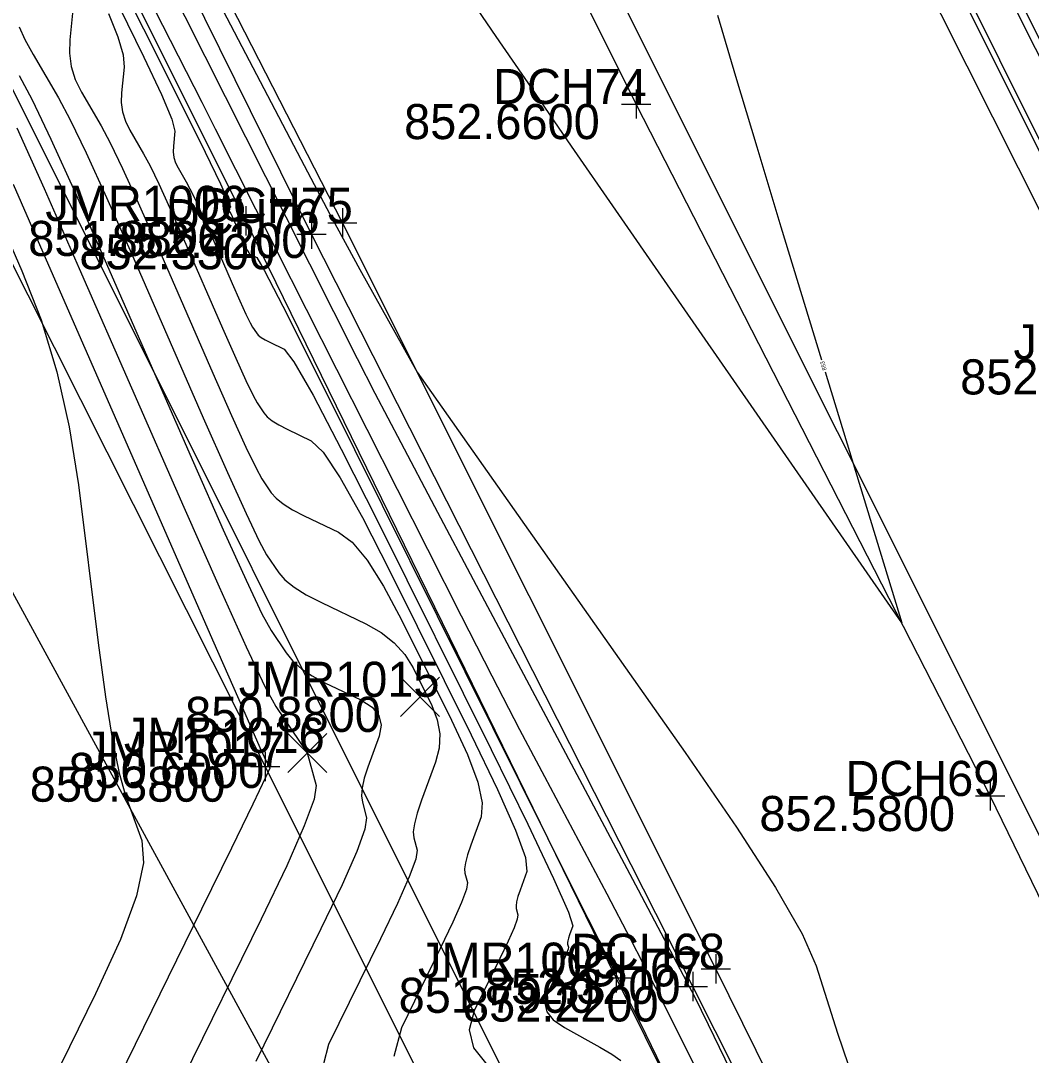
# Model space of a CAD drawing. Extents: x 1654928 to 1810050, y 486881 to 626330.
# Drawn here: x 1801345.62 to 1801380.19, y 489917.85 to 489953.22 of the extents above; entities that cross this region are included whole.
import ezdxf

# ---------------------------------------------------------------- set-up
doc = ezdxf.new("R2010")
doc.units = 0
for name, color, linetype in [('DT_X_Contour_Major', 7, 'Continuous'), ('DT_X_Contour_Minor', 7, 'Continuous'), ('PV_X_EOP', 7, 'Continuous'), ('PV_X_Shoulder', 7, 'Continuous'), ('RD_X_Fence', 7, 'Continuous'), ('RW_X_Esmt_SH', 7, 'Continuous'), ('SV_X_Break_Lines', 7, 'Continuous'), ('SV_X_Center_of_Pavt', 7, 'Continuous'), ('SV_X_CL_Survey_20', 7, 'Continuous'), ('SV_X_Occupation_Line', 7, 'Continuous'), ('SV_X_Random_Point', 7, 'Continuous'), ('SV_X_Shot_Marker', 7, 'Continuous'), ('SV_X_Text_Elevation', 7, 'Continuous'), ('SV_X_Text_Name', 7, 'Continuous')]:
    doc.layers.add(name, color=color, linetype=linetype)

msp = doc.modelspace()

# ---------------------------------------------------------------- linework, layer by layer
at = {"layer": 'DT_X_Contour_Major'}
for points in [[(1801344.553, 489964.664), (1801350.197, 489953.606), (1801351.808, 489950.439), (1801352.274, 489949.518), (1801354.342, 489945.414), (1801359.53, 489935.147), (1801360.682, 489932.876), (1801361.734, 489930.824), (1801362.685, 489928.991), (1801363.535, 489927.377), (1801365.669, 489923.365), (1801366.482, 489921.817), (1801367.323, 489920.181), (1801368.19, 489918.458), (1801369.084, 489916.647), (1801372.39, 489909.892), (1801374.021, 489906.547), (1801376.699, 489901.037), (1801377.442, 489899.52), (1801377.866, 489898.669)], [(1801345.567, 489953.015), (1801345.76, 489952.58), (1801346.041, 489952.064), (1801346.908, 489950.583), (1801347.307, 489949.834), (1801347.856, 489948.697), (1801348.554, 489947.172), (1801349.402, 489945.26), (1801351.861, 489939.643), (1801352.688, 489937.771), (1801353.324, 489936.367), (1801353.769, 489935.431), (1801354.023, 489934.963), (1801354.446, 489934.34), (1801354.656, 489934.101), (1801354.969, 489933.853), (1801355.384, 489933.595), (1801355.902, 489933.328), (1801357.42, 489932.602), (1801357.948, 489932.303), (1801358.394, 489931.952), (1801358.757, 489931.548), (1801359.039, 489931.092), (1801359.679, 489929.804), (1801359.867, 489929.321), (1801359.95, 489928.837), (1801359.929, 489928.353), (1801359.803, 489927.868), (1801359.329, 489926.575), (1801359.179, 489926.131), (1801359.084, 489925.768), (1801359.044, 489925.487), (1801359.06, 489925.287), (1801359.174, 489924.863), (1801359.129, 489924.555), (1801358.906, 489923.946), (1801358.505, 489923.039), (1801357.927, 489921.832), (1801356.15, 489918.213), (1801355.804, 489916.896)]]:
    msp.add_lwpolyline(points, dxfattribs=at)
at = {"layer": 'DT_X_Contour_Minor'}
for points in [[(1801356.249, 490000.21), (1801363.117, 489986.849), (1801364.75, 489983.671), (1801364.894, 489983.386), (1801365.16, 489982.844), (1801367.457, 489978.086), (1801370.559, 489970.96), (1801371.193, 489969.49), (1801371.765, 489968.134), (1801372.276, 489966.893), (1801372.724, 489965.767), (1801373.838, 489962.915), (1801374.395, 489961.594), (1801375.231, 489959.771), (1801376.346, 489957.446), (1801377.74, 489954.618), (1801381.828, 489946.407)], [(1801373.135, 489941.22), (1801375.755, 489932.629), (1801367.636, 489944.338), (1801365.972, 489946.74), (1801364.459, 489948.931), (1801363.097, 489950.911), (1801361.886, 489952.678), (1801358.859, 489957.108), (1801357.784, 489958.709), (1801356.828, 489960.189), (1801355.992, 489961.549), (1801355.275, 489962.787), (1801353.523, 489965.93), (1801352.836, 489967.135), (1801352.091, 489968.392), (1801351.286, 489969.701), (1801350.423, 489971.063), (1801348.041, 489974.763), (1801347.122, 489976.211), (1801346.15, 489977.776), (1801345.125, 489979.461)], [(1801344.35, 489969.1), (1801346.064, 489965.873), (1801346.684, 489964.701), (1801347.414, 489963.315), (1801352.289, 489954.042), (1801355.202, 489948.481), (1801355.772, 489947.399), (1801356.299, 489946.411), (1801356.782, 489945.517), (1801357.222, 489944.718), (1801359.175, 489941.208), (1801368.351, 489928.2), (1801370.106, 489925.653), (1801371.437, 489923.588), (1801372.345, 489922.005), (1801372.83, 489920.904), (1801373.559, 489918.61), (1801373.927, 489917.536)], [(1801345.314, 489965.023), (1801345.953, 489963.778), (1801347.496, 489960.755), (1801348.119, 489959.53), (1801348.833, 489958.122), (1801350.531, 489954.757), (1801354.681, 489946.516), (1801357.125, 489941.676), (1801357.735, 489940.489), (1801358.616, 489938.801), (1801359.77, 489936.614), (1801361.196, 489933.926), (1801366.739, 489923.501), (1801367.746, 489921.602), (1801368.383, 489920.395), (1801368.651, 489919.88), (1801369.129, 489918.901), (1801375.971, 489904.816)], [(1801346.058, 489960.371), (1801349.818, 489952.937), (1801351.051, 489950.491), (1801351.93, 489948.728), (1801352.455, 489947.648), (1801352.626, 489947.252), (1801352.61, 489947.104), (1801352.609, 489947.049), (1801352.616, 489946.996), (1801352.632, 489946.944), (1801352.658, 489946.892), (1801352.736, 489946.758), (1801352.773, 489946.69), (1801352.823, 489946.586), (1801352.886, 489946.448), (1801353.262, 489945.593), (1801353.32, 489945.465), (1801353.36, 489945.38), (1801353.383, 489945.338), (1801353.422, 489945.281), (1801353.441, 489945.259), (1801353.469, 489945.237), (1801353.507, 489945.213), (1801353.554, 489945.189), (1801353.692, 489945.123), (1801353.94, 489944.695), (1801354.579, 489943.459), (1801355.609, 489941.415), (1801357.032, 489938.564), (1801364.583, 489923.376), (1801365.434, 489921.693), (1801365.598, 489921.369), (1801365.726, 489921.117), (1801365.818, 489920.937), (1801365.874, 489920.829), (1801365.976, 489920.638), (1801366.115, 489920.359), (1801366.456, 489919.666), (1801366.999, 489918.559), (1801367.744, 489917.038)], [(1801376.832, 489959.84), (1801381.747, 489950.048)], [(1801347.426, 489953.823), (1801347.293, 489952.57), (1801347.281, 489952.105), (1801347.344, 489951.65), (1801347.482, 489951.206), (1801347.696, 489950.771), (1801348.365, 489949.627), (1801348.673, 489949.048), (1801349.098, 489948.169), (1801349.637, 489946.991), (1801350.292, 489945.513), (1801352.193, 489941.173), (1801352.831, 489939.726), (1801353.323, 489938.641), (1801353.667, 489937.918), (1801353.863, 489937.557), (1801354.19, 489937.075), (1801354.353, 489936.891), (1801354.594, 489936.699), (1801354.915, 489936.5), (1801355.315, 489936.293), (1801356.488, 489935.732), (1801356.953, 489935.387), (1801357.468, 489934.773), (1801358.033, 489933.889), (1801358.648, 489932.736), (1801360.355, 489929.303), (1801360.899, 489928.131), (1801361.249, 489927.19), (1801361.406, 489926.481), (1801361.37, 489926.003), (1801361.016, 489925.037), (1801360.904, 489924.705), (1801360.833, 489924.434), (1801360.803, 489924.224), (1801360.814, 489924.075), (1801360.9, 489923.759), (1801360.866, 489923.528), (1801360.699, 489923.074), (1801360.4, 489922.396), (1801359.969, 489921.495), (1801358.642, 489918.793), (1801358.383, 489917.808)], [(1801348.982, 489953.689), (1801349.833, 489951.976), (1801350.436, 489950.697), (1801350.789, 489949.853), (1801350.893, 489949.442), (1801350.838, 489948.926), (1801350.833, 489948.735), (1801350.859, 489948.547), (1801350.916, 489948.364), (1801351.004, 489948.185), (1801351.279, 489947.714), (1801351.406, 489947.476), (1801351.581, 489947.114), (1801351.803, 489946.629), (1801352.073, 489946.02), (1801352.855, 489944.233), (1801353.118, 489943.637), (1801353.321, 489943.191), (1801353.462, 489942.893), (1801353.543, 489942.744), (1801353.678, 489942.546), (1801353.745, 489942.47), (1801353.844, 489942.391), (1801353.976, 489942.309), (1801354.141, 489942.224), (1801354.624, 489941.993), (1801354.963, 489941.555), (1801355.616, 489940.414), (1801356.584, 489938.571), (1801357.867, 489936.026), (1801361.708, 489928.3), (1801362.963, 489925.751), (1801363.847, 489923.897), (1801364.36, 489922.737), (1801364.503, 489922.273), (1801364.389, 489921.962), (1801364.353, 489921.855), (1801364.33, 489921.768), (1801364.32, 489921.7), (1801364.324, 489921.652), (1801364.352, 489921.55), (1801364.341, 489921.476), (1801364.287, 489921.33), (1801364.191, 489921.112), (1801364.052, 489920.821), (1801363.624, 489919.951), (1801363.541, 489919.634), (1801363.611, 489919.336), (1801363.836, 489919.057), (1801364.214, 489918.796), (1801365.427, 489918.127), (1801365.834, 489917.888), (1801366.145, 489917.672)], [(1801348.616, 489953.461), (1801348.941, 489952.666), (1801349.123, 489952.057), (1801349.16, 489951.633), (1801349.066, 489950.748), (1801349.057, 489950.42), (1801349.101, 489950.099), (1801349.199, 489949.785), (1801349.35, 489949.478), (1801349.822, 489948.67), (1801350.04, 489948.262), (1801350.339, 489947.641), (1801350.72, 489946.81), (1801351.182, 489945.767), (1801352.524, 489942.703), (1801352.975, 489941.682), (1801353.322, 489940.916), (1801353.565, 489940.406), (1801353.703, 489940.15), (1801353.934, 489939.81), (1801354.049, 489939.68), (1801354.219, 489939.545), (1801354.446, 489939.404), (1801354.728, 489939.258), (1801355.556, 489938.862), (1801355.958, 489938.471), (1801356.542, 489937.594), (1801357.308, 489936.23), (1801358.257, 489934.381), (1801361.031, 489928.802), (1801361.931, 489926.941), (1801362.548, 489925.543), (1801362.883, 489924.609), (1801362.936, 489924.138), (1801362.702, 489923.5), (1801362.628, 489923.28), (1801362.581, 489923.101), (1801362.562, 489922.962), (1801362.569, 489922.864), (1801362.626, 489922.655), (1801362.603, 489922.502), (1801362.493, 489922.202), (1801362.296, 489921.754), (1801362.01, 489921.158), (1801361.133, 489919.372), (1801360.962, 489918.721), (1801361.106, 489918.109), (1801361.567, 489917.536)], [(1801369.449, 489953.407), (1801370.068, 489951.322), (1801370.793, 489948.911), (1801371.625, 489946.172), (1801373.013, 489941.622)], [(1801345.566, 489951.342), (1801346.006, 489950.509), (1801346.643, 489949.175), (1801347.478, 489947.341), (1801348.511, 489945.006), (1801351.53, 489938.113), (1801352.545, 489935.815), (1801353.325, 489934.092), (1801353.871, 489932.943), (1801354.183, 489932.369), (1801354.703, 489931.604), (1801354.931, 489931.325), (1801355.226, 489931.063), (1801355.588, 489930.818), (1801356.016, 489930.588), (1801357.248, 489929.999), (1801357.634, 489929.756), (1801357.868, 489929.468), (1801357.95, 489929.136), (1801357.88, 489928.759), (1801357.49, 489927.695), (1801357.368, 489927.321), (1801357.297, 489926.997), (1801357.276, 489926.723), (1801357.305, 489926.498), (1801357.449, 489925.967), (1801357.391, 489925.581), (1801357.112, 489924.819), (1801356.61, 489923.681), (1801355.886, 489922.168), (1801353.659, 489917.634)], [(1801345.484, 489949.562), (1801346.416, 489947.486), (1801347.621, 489944.752), (1801351.198, 489936.583), (1801352.401, 489933.86), (1801353.326, 489931.817), (1801353.973, 489930.456), (1801354.343, 489929.775), (1801355.421, 489928.189), (1801355.723, 489927.072), (1801355.654, 489926.607), (1801355.318, 489925.691), (1801354.715, 489924.324), (1801353.845, 489922.505), (1801351.168, 489917.055)], [(1801343.748, 489949.023), (1801345.654, 489944.672), (1801346.311, 489942.99), (1801346.853, 489941.21), (1801347.28, 489939.331), (1801347.592, 489937.353), (1801348.27, 489931.946), (1801348.519, 489930.099), (1801348.757, 489928.615), (1801348.984, 489927.493), (1801349.2, 489926.733), (1801349.76, 489925.189), (1801349.818, 489924.427), (1801349.574, 489923.3), (1801349.027, 489921.809), (1801348.177, 489919.952), (1801345.505, 489914.513)], [(1801345.354, 489947.632), (1801346.731, 489944.499), (1801352.227, 489931.949), (1801353.204, 489929.724), (1801353.799, 489928.376), (1801354.011, 489927.906), (1801354.086, 489927.794), (1801354.102, 489927.767), (1801354.113, 489927.741), (1801354.121, 489927.718), (1801354.137, 489927.66), (1801353.995, 489927.343), (1801353.559, 489926.434), (1801352.828, 489924.934), (1801351.803, 489922.842), (1801348.676, 489916.476)]]:
    msp.add_lwpolyline(points, dxfattribs=at)
at = {"layer": 'PV_X_EOP'}
for points in [[(1801533.684, 489642.188), (1801522.484, 489664.508), (1801511.881, 489685.341), (1801500.299, 489708.684), (1801491.104, 489726.659), (1801480.832, 489747.383), (1801466.882, 489774.659), (1801456.506, 489795.715), (1801444.637, 489819.009), (1801433.258, 489841.444), (1801422.029, 489863.995), (1801410.905, 489885.928), (1801399.817, 489908.089), (1801388.576, 489930.656), (1801376.228, 489955.188), (1801366.008, 489975.62), (1801354.725, 489997.894)], [(1801513.785, 489634.043), (1801503.26, 489654.965), (1801492.692, 489675.84), (1801481.803, 489697.704), (1801472.078, 489717.629), (1801460.782, 489739.414), (1801448.005, 489764.97), (1801436.553, 489786.89), (1801425.237, 489809.697), (1801414.345, 489830.894), (1801402.21, 489854.742), (1801391.781, 489876.056), (1801380.008, 489899.32), (1801369.395, 489920.807), (1801356.62, 489946.308), (1801346.845, 489965.404), (1801335.257, 489988.444)]]:
    msp.add_lwpolyline(points, dxfattribs=at)
at = {"layer": 'PV_X_Shoulder'}
for points in [[(1801534.471, 489642.456), (1801522.963, 489664.954), (1801512.6, 489685.485), (1801500.973, 489709.112), (1801491.766, 489727.019), (1801481.526, 489747.768), (1801467.484, 489775.07), (1801457.116, 489796.092), (1801445.57, 489819.398), (1801434.029, 489841.927), (1801422.682, 489864.343), (1801411.885, 489886.25), (1801400.664, 489908.455), (1801366.703, 489976.232), (1801355.676, 489998.276)], [(1801513.053, 489633.484), (1801502.425, 489654.401), (1801492.155, 489675.438), (1801481.048, 489697.245), (1801471.095, 489717.056), (1801459.974, 489738.844), (1801446.996, 489764.517), (1801435.938, 489786.184), (1801424.33, 489809.156), (1801413.386, 489830.353), (1801401.606, 489854.259), (1801390.811, 489875.349), (1801379.301, 489898.985), (1801368.607, 489920.204), (1801355.561, 489945.921), (1801346.174, 489964.922), (1801334.144, 489988.199)]]:
    msp.add_lwpolyline(points, dxfattribs=at)
at = {"layer": 'RD_X_Fence'}
msp.add_lwpolyline([(1801327.157, 489980.825), (1801341.337, 489952.815), (1801353.978, 489927.719), (1801368.649, 489898.399), (1801382.749, 489869.731), (1801399.284, 489836.538), (1801405.615, 489823.327), (1801393.757, 489823.044), (1801375.98, 489823.449), (1801361.092, 489823.97), (1801335.059, 489824.221), (1801306.244, 489824.992)], dxfattribs=at)
at = {"layer": 'RW_X_Esmt_SH'}
msp.add_line((1801533.563, 489574.54), (1801308.538, 490024.454), dxfattribs=at)
at = {"layer": 'SV_X_Break_Lines'}
for points in [[(1801445.791, 489822.136), (1801441.193, 489830.46), (1801435.211, 489842.68), (1801424.275, 489864.659), (1801412.811, 489886.984), (1801408.709, 489897.161), (1801400.001, 489913.183), (1801395.188, 489923.674), (1801385.653, 489941.642), (1801375.001, 489962.91), (1801364.942, 489983.144), (1801355.514, 490001.536)], [(1801419.479, 489816.264), (1801413.606, 489827.582), (1801399.229, 489854.903), (1801388.205, 489875.792), (1801377.391, 489897.446), (1801365.991, 489920.501), (1801353.319, 489946.375), (1801342.526, 489967.898), (1801332.595, 489987.823)]]:
    msp.add_lwpolyline(points, dxfattribs=at)
at = {"layer": 'SV_X_Center_of_Pavt'}
msp.add_lwpolyline([(1801523.585, 489638.313), (1801512.853, 489659.481), (1801502.374, 489680.412), (1801490.819, 489703.952), (1801481.428, 489721.68), (1801470.803, 489742.834), (1801457.335, 489769.613), (1801446.389, 489792.464), (1801435.307, 489813.792), (1801423.54, 489836.522), (1801412.234, 489859.298), (1801401.202, 489881.345), (1801390.005, 489903.67), (1801378.784, 489926.715), (1801366.669, 489950.371), (1801356.567, 489970.63), (1801345.517, 489992.708)], dxfattribs=at)
at = {"layer": 'SV_X_CL_Survey_20'}
msp.add_line((1802886.975, 486913.246), (1801128.538, 490429.055), dxfattribs=at)
msp.add_line((1802886.975, 486913.246), (1801128.538, 490429.055), dxfattribs=at)
at = {"layer": 'SV_X_Occupation_Line'}
msp.add_lwpolyline([(1801323.637, 489975.339), (1801342.746, 489938.404), (1801356.309, 489913.548), (1801376.911, 489872.203), (1801387.619, 489838.687), (1801379.855, 489831.976), (1801347.713, 489831.536), (1801304.639, 489830.454)], dxfattribs=at)
at = {"layer": 'SV_X_Random_Point'}
for p, q in [((1801358.606, 489929.437), (1801359.94, 489930.772)), ((1801358.606, 489930.772), (1801359.94, 489929.437)), ((1801354.754, 489927.521), (1801356.087, 489928.856)), ((1801354.754, 489928.856), (1801356.087, 489927.521))]:
    msp.add_line(p, q, dxfattribs=at)
at = {"layer": 'SV_X_Shot_Marker'}
for p, q in [((1801366.669, 489950.871), (1801366.669, 489949.871)), ((1801366.169, 489950.371), (1801367.169, 489950.371)), ((1801366.669, 489950.371), (1801366.669, 489950.371)), ((1801353.319, 489946.875), (1801353.319, 489945.875)), ((1801356.62, 489946.808), (1801356.62, 489945.808)), ((1801352.819, 489946.375), (1801353.819, 489946.375)), ((1801353.319, 489946.375), (1801353.319, 489946.375)), ((1801355.561, 489946.421), (1801355.561, 489945.421)), ((1801356.12, 489946.308), (1801357.12, 489946.308)), ((1801356.62, 489946.308), (1801356.62, 489946.308)), ((1801355.061, 489945.921), (1801356.061, 489945.921)), ((1801355.561, 489945.921), (1801355.561, 489945.921)), ((1801353.978, 489928.219), (1801353.978, 489927.219)), ((1801353.478, 489927.719), (1801354.478, 489927.719)), ((1801353.978, 489927.719), (1801353.978, 489927.719)), ((1801378.784, 489927.215), (1801378.784, 489926.215)), ((1801378.284, 489926.715), (1801379.284, 489926.715)), ((1801378.784, 489926.715), (1801378.784, 489926.715)), ((1801369.395, 489921.307), (1801369.395, 489920.307)), ((1801365.991, 489921.001), (1801365.991, 489920.001)), ((1801368.607, 489920.704), (1801368.607, 489919.704)), ((1801368.895, 489920.807), (1801369.895, 489920.807)), ((1801369.395, 489920.807), (1801369.395, 489920.807)), ((1801365.491, 489920.501), (1801366.491, 489920.501)), ((1801365.991, 489920.501), (1801365.991, 489920.501)), ((1801368.107, 489920.204), (1801369.107, 489920.204)), ((1801368.607, 489920.204), (1801368.607, 489920.204))]:
    msp.add_line(p, q, dxfattribs=at)

# ---------------------------------------------------------------- texts
at = {"layer": 'DT_X_Contour_Minor'}
msp.add_text('853', height=0.14, rotation=106.9594, dxfattribs=at).set_placement((1801373.188, 489941.289))
at = {"layer": 'SV_X_Text_Elevation'}
for s, p in [('852.6600', (1801358.732, 489949.171)), ('851.8800', (1801345.875, 489945.175)), ('852.4200', (1801348.731, 489945.108)), ('852.3300', (1801347.625, 489944.72)), ('852.3200', (1801377.754, 489940.442)), ('850.8800', (1801351.242, 489928.905)), ('850.6000', (1801347.257, 489926.989)), ('850.3800', (1801345.928, 489926.519)), ('852.5800', (1801370.885, 489925.515)), ('852.3200', (1801361.496, 489919.607)), ('851.7900', (1801358.546, 489919.301)), ('852.2200', (1801360.747, 489919.004))]:
    msp.add_text(s, height=1.2, dxfattribs=at).set_placement(p)
at = {"layer": 'SV_X_Text_Name'}
for s, p in [('DCH74', (1801361.775, 489950.371)), ('JMR1006', (1801346.46, 489946.375)), ('DCH75', (1801351.717, 489946.308)), ('DCH76', (1801350.582, 489945.921)), ('JMR1152', (1801379.579, 489941.642)), ('JMR1015', (1801353.076, 489930.105)), ('JMR1016', (1801349.148, 489928.189)), ('JMR1017', (1801347.781, 489927.719)), ('DCH69', (1801373.833, 489926.715)), ('DCH68', (1801364.444, 489920.807)), ('JMR1005', (1801359.208, 489920.501)), ('DCH67', (1801363.666, 489920.204))]:
    msp.add_text(s, height=1.2, dxfattribs=at).set_placement(p)

doc.saveas('drawing.dxf')
